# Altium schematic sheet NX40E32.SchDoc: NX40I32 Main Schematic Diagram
size A3; DocumentNumber: 2; SheetNumber: 2; SheetTotal: 2
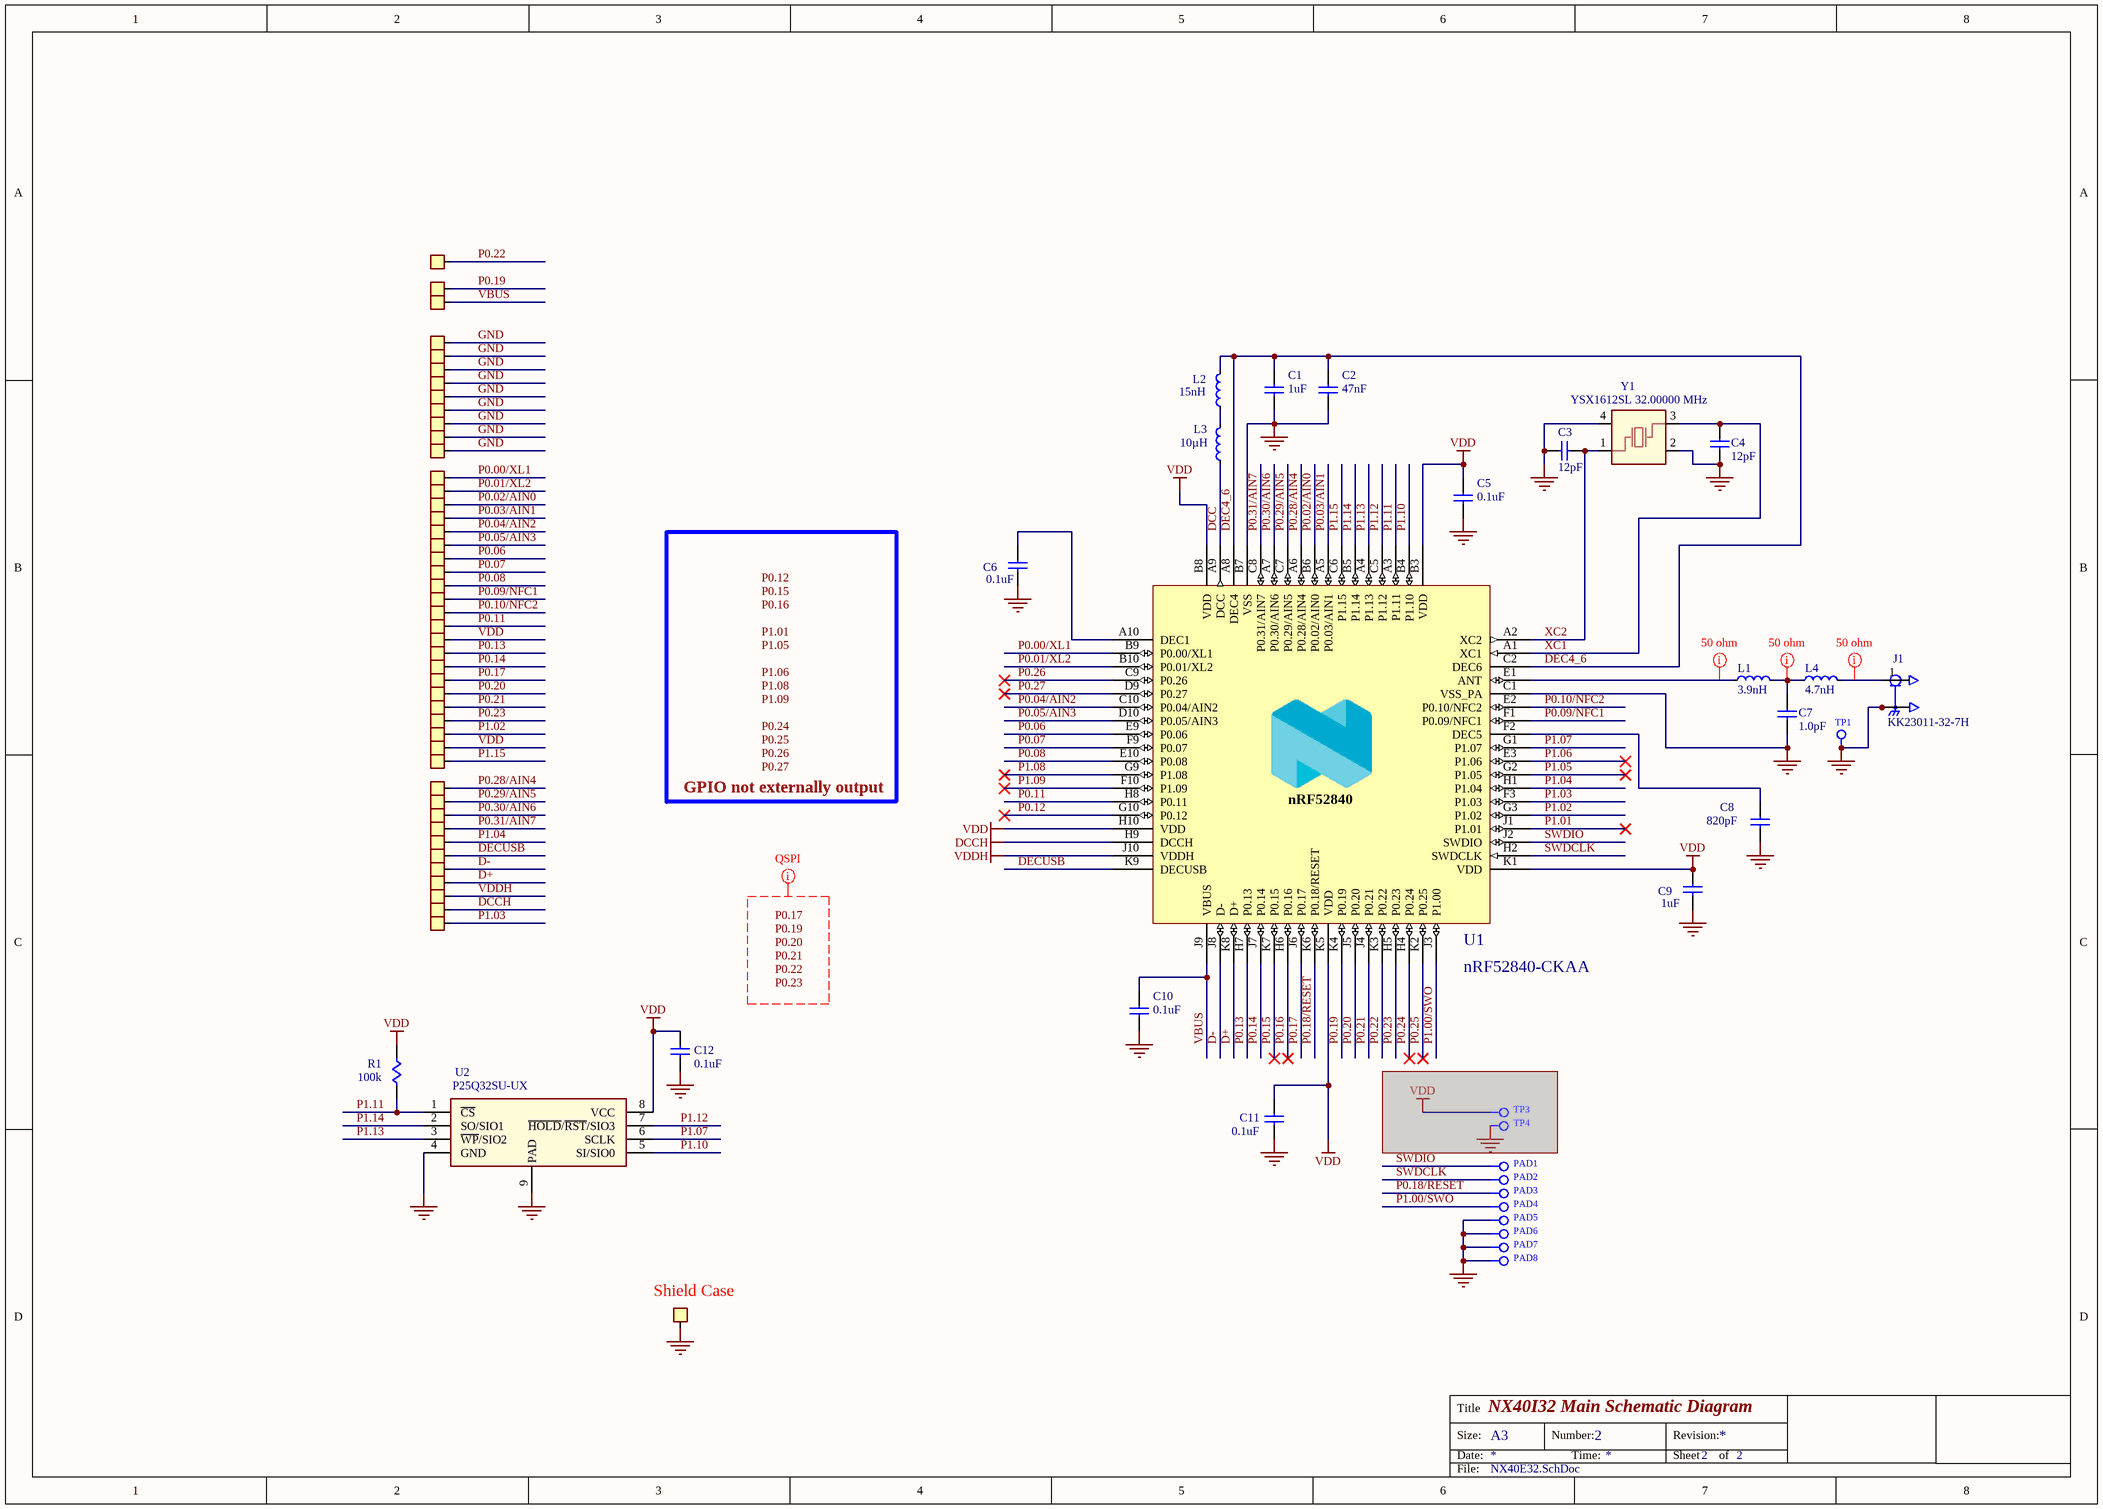
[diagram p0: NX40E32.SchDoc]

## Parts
C1  1uF  [CAP 0201/0603X03L_NX]
C2  47nF  [CAP 0201/0603X03L_NX]
C3  12pF  [CAP 0201/0603X03L_NX]
C4  12pF  [CAP 0201/0603X03L_NX]
C5  0.1uF  [CAP 0201/0603X03L_NX]
C6  0.1uF  [CAP 0201/0603X03L_NX]
C7  1.0pF  [CAP 0201/0603X03L_NX]
C8  820pF  [CAP 0201/0603X03L_NX]
C9  1uF  [CAP 0201/0603X03L_NX]
C10  0.1uF  [CAP 0201/0603X03L_NX]
C11  0.1uF  [CAP 0201/0603X03L_NX]
C12  0.1uF  [CAP 0201/0603X03L_NX]
J1  KK23011-32-7H  [IPEX 3x3_23011]
L1  3.9nH  [IND 0201/0603X03L_NX]
L2  15nH  [IND 0402/1005_NX]
L3  10µH  [IND 0603/1608X08L_NX]
L4  4.7nH  [IND 0201/0603X03L_NX]
P1  PAD SQUARE  [PAD_0.6X0.3]  (value not drawn)
P2  PAD SQUARE  [PAD_0.6X0.3]  (value not drawn)
P3  PAD SQUARE  [PAD_0.6X0.3]  (value not drawn)
P4  PAD SQUARE  [PAD_0.6X0.3]  (value not drawn)
P5  PAD SQUARE  [PAD_0.6X0.3]  (value not drawn)
P6  PAD SQUARE  [PAD_0.6X0.3]  (value not drawn)
P7  PAD SQUARE  [PAD_0.6X0.3]  (value not drawn)
P8  PAD SQUARE  [PAD_0.6X0.3]  (value not drawn)
P9  PAD SQUARE  [PAD_0.6X0.3]  (value not drawn)
P10  PAD SQUARE  [PAD_0.6X0.3]  (value not drawn)
P11  PAD SQUARE  [PAD_0.6X0.3]  (value not drawn)
P12  PAD SQUARE  [PAD_0.6X0.3]  (value not drawn)
P13  PAD SQUARE  [PAD_0.6X0.3]  (value not drawn)
P14  PAD SQUARE  [PAD_0.6X0.3]  (value not drawn)
P15  PAD SQUARE  [PAD_0.6X0.3]  (value not drawn)
P16  PAD SQUARE  [PAD_0.6X0.3]  (value not drawn)
P17  PAD SQUARE  [PAD_0.6X0.3]  (value not drawn)
P18  PAD SQUARE  [PAD_0.6X0.3]  (value not drawn)
P19  PAD SQUARE  [PAD_0.6X0.3]  (value not drawn)
P20  PAD SQUARE  [PAD_0.6X0.3]  (value not drawn)
P21  PAD SQUARE  [PAD_0.6X0.3]  (value not drawn)
P22  PAD SQUARE  [PAD_0.6X0.3]  (value not drawn)
P23  PAD SQUARE  [PAD_0.6X0.3]  (value not drawn)
P24  PAD SQUARE  [PAD_0.6X0.3]  (value not drawn)
P25  PAD SQUARE  [PAD_0.6X0.3]  (value not drawn)
P26  PAD SQUARE  [PAD_0.6X0.3]  (value not drawn)
P27  PAD SQUARE  [PAD_0.6X0.3]  (value not drawn)
P28  PAD SQUARE  [PAD_0.6X0.3]  (value not drawn)
P29  PAD SQUARE  [PAD_0.6X0.3]  (value not drawn)
P30  PAD SQUARE  [PAD_0.6X0.3]  (value not drawn)
P31  PAD SQUARE  [PAD_0.6X0.3]  (value not drawn)
P32  PAD SQUARE  [PAD_0.6X0.3]  (value not drawn)
P33  PAD SQUARE  [PAD_0.6X0.3]  (value not drawn)
P34  PAD SQUARE  [PAD_0.6X0.3]  (value not drawn)
P35  PAD SQUARE  [PAD_0.6X0.3]  (value not drawn)
P36  PAD SQUARE  [PAD_0.6X0.3]  (value not drawn)
P37  PAD SQUARE  [PAD_0.6X0.3]  (value not drawn)
P38  PAD SQUARE  [PAD_0.6X0.3]  (value not drawn)
P39  PAD SQUARE  [PAD_0.6X0.3]  (value not drawn)
P40  PAD SQUARE  [PAD_0.6X0.3]  (value not drawn)
P41  PAD SQUARE  [PAD_0.6X0.3]  (value not drawn)
P42  PAD SQUARE  [PAD_0.6X0.3]  (value not drawn)
P43  PAD SQUARE  [PAD_0.6X0.3]  (value not drawn)
P44  PAD SQUARE  [PAD_0.6X0.3]  (value not drawn)
P45  PAD SQUARE  [PAD_0.6X0.3]  (value not drawn)
PAD1  5010  [pad_0.6x0.6]  (value not drawn)  (no BOM)
PAD2  5010  [pad_0.6x0.6]  (value not drawn)  (no BOM)
PAD3  5010  [pad_0.6x0.6]  (value not drawn)  (no BOM)
PAD4  5010  [pad_0.6x0.6]  (value not drawn)  (no BOM)
PAD5  5010  [pad_0.6x0.6]  (value not drawn)  (no BOM)
PAD6  5010  [pad_0.6x0.6]  (value not drawn)  (no BOM)
PAD7  5010  [pad_0.6x0.6]  (value not drawn)  (no BOM)
PAD8  5010  [pad_0.6x0.6]  (value not drawn)  (no BOM)
R1  100k  [RES 0201/0603]
T1  SHILED CASE  [Shield_can_Korlinx]  (value not drawn)  (no BOM)
TP1  5010  [TP / 0.3]  (value not drawn)  (no BOM)
TP3  5010  [pad_0.7x0.7]  (value not drawn)  (no BOM)  (masked out: inside a compile mask, not in the netlist)
TP4  5010  [pad_0.7x0.7]  (value not drawn)  (no BOM)  (masked out: inside a compile mask, not in the netlist)
U1  nRF52840-CKAA  [BGA94C35P10X10_352X356X50]
U2  P25Q32SU-UX  [USON-8 2X3 /PSON50P300X200X60-9N]
Y1  YSX1612SL 32.00000 MHz  [XTAL/1612]

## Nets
DCCH: P44.1 U1.H9(DCCH)
GND: C1.1 C2.2 C3.1 C4.2 C5.2 C6.2 C7.1 C8.1 C9.2 C10.2 C11.1 C12.1 J1.2(GND) J1.3(GND) P3.1 P4.1 P5.1 P6.1 P7.1 P8.1 P11.1 P16.1 P35.1 PAD5.1 PAD6.1 PAD7.1 PAD8.1 T1.1 TP1.1 U1.B7(VSS) U1.C1(VSS_PA) U1.C4(GND) U1.D3(GND) U1.D4(GND) U1.D5(GND) U1.D6(GND) U1.D7(GND) U1.D8(GND) U1.E4(GND) U1.E5(GND) U1.E6(GND) U1.E7(GND) U1.E8(GND) U1.F4(GND) U1.F5(GND) U1.F6(GND) U1.F7(GND) U1.F8(GND) U1.G4(GND) U1.G5(GND) U1.G6(GND) U1.G7(GND) U1.G8(GND) U1.K10(GND) U2.4(GND) U2.9(PAD) Y1.2(GND) Y1.4(GND)
VDD: C5.1 C9.1 C11.2 C12.2 P12.1 P27.1 R1.2 U1.B3(VDD) U1.B8(VDD) U1.H10(VDD) U1.K1(VDD) U1.K5(VDD) U2.8(VCC)
VDDH: P43.1 U1.J10(VDDH)
D+: P42.1 U1.K8(D+)
D-: P41.1 U1.J8(D-)
DCC: L3.1 U1.A9(DCC)
DEC4_6: C1.2 C2.1 L2.2 U1.A8(DEC4) U1.C2(DEC6)
DECUSB: P40.1 U1.K9(DECUSB)
P0.00/XL1: P15.1 U1.B9(P0.00/XL1)
P0.01/XL2: P17.1 U1.B10(P0.01/XL2)
P0.02/AIN0: P18.1 U1.B6(P0.02/AIN0)
P0.03/AIN1: P19.1 U1.A5(P0.03/AIN1)
P0.04/AIN2: P20.1 U1.C10(P0.04/AIN2)
P0.05/AIN3: P21.1 U1.D10(P0.05/AIN3)
P0.06: P22.1 U1.E9(P0.06)
P0.07: P10.1 U1.F9(P0.07)
P0.08: P23.1 U1.E10(P0.08)
P0.09/NFC1: P24.1 U1.F1(P0.09/NFC1)
P0.10/NFC2: P25.1 U1.E2(P0.10/NFC2)
P0.11: P26.1 U1.H8(P0.11)
P0.12: U1.G10(P0.12)
P0.13: P28.1 U1.H7(P0.13)
P0.14: P29.1 U1.J7(P0.14)
P0.15: U1.K7(P0.15)
P0.16: U1.H6(P0.16)
P0.17: P30.1 U1.J6(P0.17)
P0.18/RESET: PAD3.1 U1.K6(P0.18/RESET)
P0.19: P1.1 U1.K4(P0.19)
P0.20: P34.1 U1.J5(P0.20)
P0.21: P32.1 U1.J4(P0.21)
P0.22: P9.1 U1.K3(P0.22)
P0.23: P31.1 U1.H5(P0.23)
P0.24: U1.H4(P0.24)
P0.25: U1.K2(P0.25)
P0.26: U1.C9(P0.26)
P0.27: U1.D9(P0.27)
P0.28/AIN4: P14.1 U1.A6(P0.28/AIN4)
P0.29/AIN5: P13.1 U1.C7(P0.29/AIN5)
P0.30/AIN6: P37.1 U1.A7(P0.30/AIN6)
P0.31/AIN7: P38.1 U1.C8(P0.31/AIN7)
P1.00/SWO: PAD4.1 U1.J3(P1.00)
P1.01: U1.J1(P1.01)
P1.02: P36.1 U1.G3(P1.02)
P1.03: P45.1 U1.F3(P1.03)
P1.04: P39.1 U1.H1(P1.04)
P1.05: U1.G2(P1.05)
P1.06: U1.E3(P1.06)
P1.07: U1.G1(P1.07) U2.6(SCLK)
P1.08: U1.G9(P1.08)
P1.09: U1.F10(P1.09)
P1.10: U1.B4(P1.10) U2.5(SI/SIO0)
P1.11: R1.1 U1.A3(P1.11) U2.1(~{CS})
P1.12: U1.C5(P1.12) U2.7(~{HOLD}/~{RST}/SIO3)
P1.13: U1.A4(P1.13) U2.3(~{WP}/SIO2)
P1.14: U1.B5(P1.14) U2.2(SO/SIO1)
P1.15: P33.1 U1.C6(P1.15)
SWDCLK: PAD2.1 U1.H2(SWDCLK)
SWDIO: PAD1.1 U1.J2(SWDIO)
VBUS: C10.1 P2.1 U1.J9(VBUS)
XC1: C4.1 U1.A1(XC1) Y1.3(OSC2)
XC2: C3.2 U1.A2(XC2) Y1.1(OSC1)
NetC6_1: C6.1 U1.A10(DEC1)
NetC7_2: C7.2 L1.2 L4.1
NetC8_2: C8.2 U1.F2(DEC5)
NetJ1_1: J1.1(SIGNAL) L4.2
NetL1_1: L1.1 U1.E1(ANT)
NetL2_1: L2.1 L3.2

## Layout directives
net class 50s; rule Width Constraint [Pref Width = 6.2mil    Min Width = 6.2mil    Max Width = 6.2mil]: NetC7_2, NetJ1_1, NetL1_1
net class QSPI: P0.17, P0.19, P0.20, P0.21, P0.22, P0.23

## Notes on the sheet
- GPIO not externally output
- (near T1) Shield Case
- Labels drawn without touching a wire or pin: P0.12, P0.15, P0.16, P0.17, P0.19, P0.20, P0.21, P0.22, P0.23, P0.24, P0.25, P0.26, P0.27, P1.01, P1.05, P1.06, P1.08, P1.09

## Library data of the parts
C1 = C0201-10n: Capacitor, X5R, ±10%; Part number IPS: 00000003480; Note: 10V; Artikkelnr Noca: N.A.
C2 C6 C9 C10 = C0603-4µ7-6.3V-X7R: Capacitor, X5R, ±10%
C3 C4 = C0402-12p: Capacitor, NP0, ±2%; Manufacturer: N.A.; Part number IPS: 00000002398; Note: 50V; Artikkelnr Noca: 20029159; Pad Count: 2
C5 = C0603-4µ7-6.3V-X7R: Capacitor, X7R, ±10%
C7 C8 C12 = C0402-100p: Capacitor, NP0, ±5%; Manufacturer: N.A.; Part number IPS: 00000002361; Note: 50V; Artikkelnr Noca: 20029135; Pad Count: 2
C11 = C0402-100p: Capacitor, X5R, ±10%; Manufacturer: N.A.; Part number IPS: 00000002361; Note: 50V; Artikkelnr Noca: 20029135; Pad Count: 2
J1 = 20449-001E-03: IPEX Connector; MF: I-PEX
L1 L2 L4 = L0201-4n7: Inductor; Manufacturer: Murata; Manufacturer Part Number: LQP03TN4N7H02D; Part number IPS: 00000001792; Note: N.A.; Pad Count: 2
L3 = L0603-10µ: Chip inductor, IDC,min = 50 mA, ±20%
PAD1-PAD8 TP1 TP3 TP4 = TP: Test Point; Manufacturer: Keystone; CompType: Test Point Loop; ContactFinish: Silver
R1 = Res1: Resistor; Value: 1K
T1 = PAD SQUARE
U1 = nRF52840-CKAA: Multi-protocol Bluetooth Low Energy, IEEE 802.15.4, ANT and 2.4GHz proprietary system-on-chip; Pad Count: 94
U2 = P25Q32SU
Y1 = OSC-4: BOM_Manufacturer: TKD; BOM_Manufacturer Part: SX32Y025000BC1T; nameAlias: Frequency; Contributor: LCSC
